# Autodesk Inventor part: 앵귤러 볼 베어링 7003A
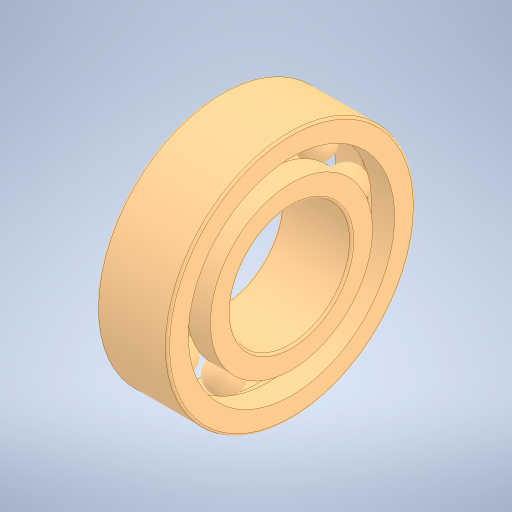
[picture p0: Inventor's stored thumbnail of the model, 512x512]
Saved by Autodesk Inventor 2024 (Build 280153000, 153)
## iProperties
Created: 2024-11
Part Number: 앵귤러 볼 베어링 7003A
Material: 강철, 연강
Description: 앵귤러 콘택트 볼 베어링
Document SubType Name: Modeling
Designer: user
Density: 7.85 g/cm^3
Appearance: 기본값
Author: jhkim
Sending System: Autodesk Inventor 2025
Preprocessor: ST-DEVELOPER v20
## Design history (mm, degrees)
node "앵귤러 볼 베어링 7003A1"
node "솔리드1"
node "솔리드2"
node "솔리드3"
node "솔리드4"
node "솔리드5"
node "솔리드6"
node "솔리드7"
node "솔리드8"
node "솔리드9"
node "솔리드10"
node "솔리드11"
body "Solid1"
node "Solid1:1"
node "Solid1:2"
node "Solid1:3"
node "Solid1:4"
node "Solid1:5"
node "Solid1:6"
node "Solid1:7"
node "Solid1:8"
node "Solid1:9"
node "Solid1:10"
